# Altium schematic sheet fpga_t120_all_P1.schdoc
size 839 x 594 mm; Symbol: Drawing-Symbol_A4; @Project Name: FPGA_motors_V3_1; @Page Count: 1; @Update Date: 2026-01-04; @Create Date: 2025-12-23; @Schematic Name: fpga_t120_all_p; @Page No: 1; @Page Name: P1; Company: EasyEDA.com; Version: V1.0; Page Size: A4; @Create Time: 13:22:03; @Update Time: 11:05:47; Border: 1; Width: 3304; Height: 2338; Region Start: 1; X Region Count: 6; Y Region Count: 4; Blade Width: 10; Title Block Position: 3; @Board Name: PCB6; Device: Drawing-Symbol_A4
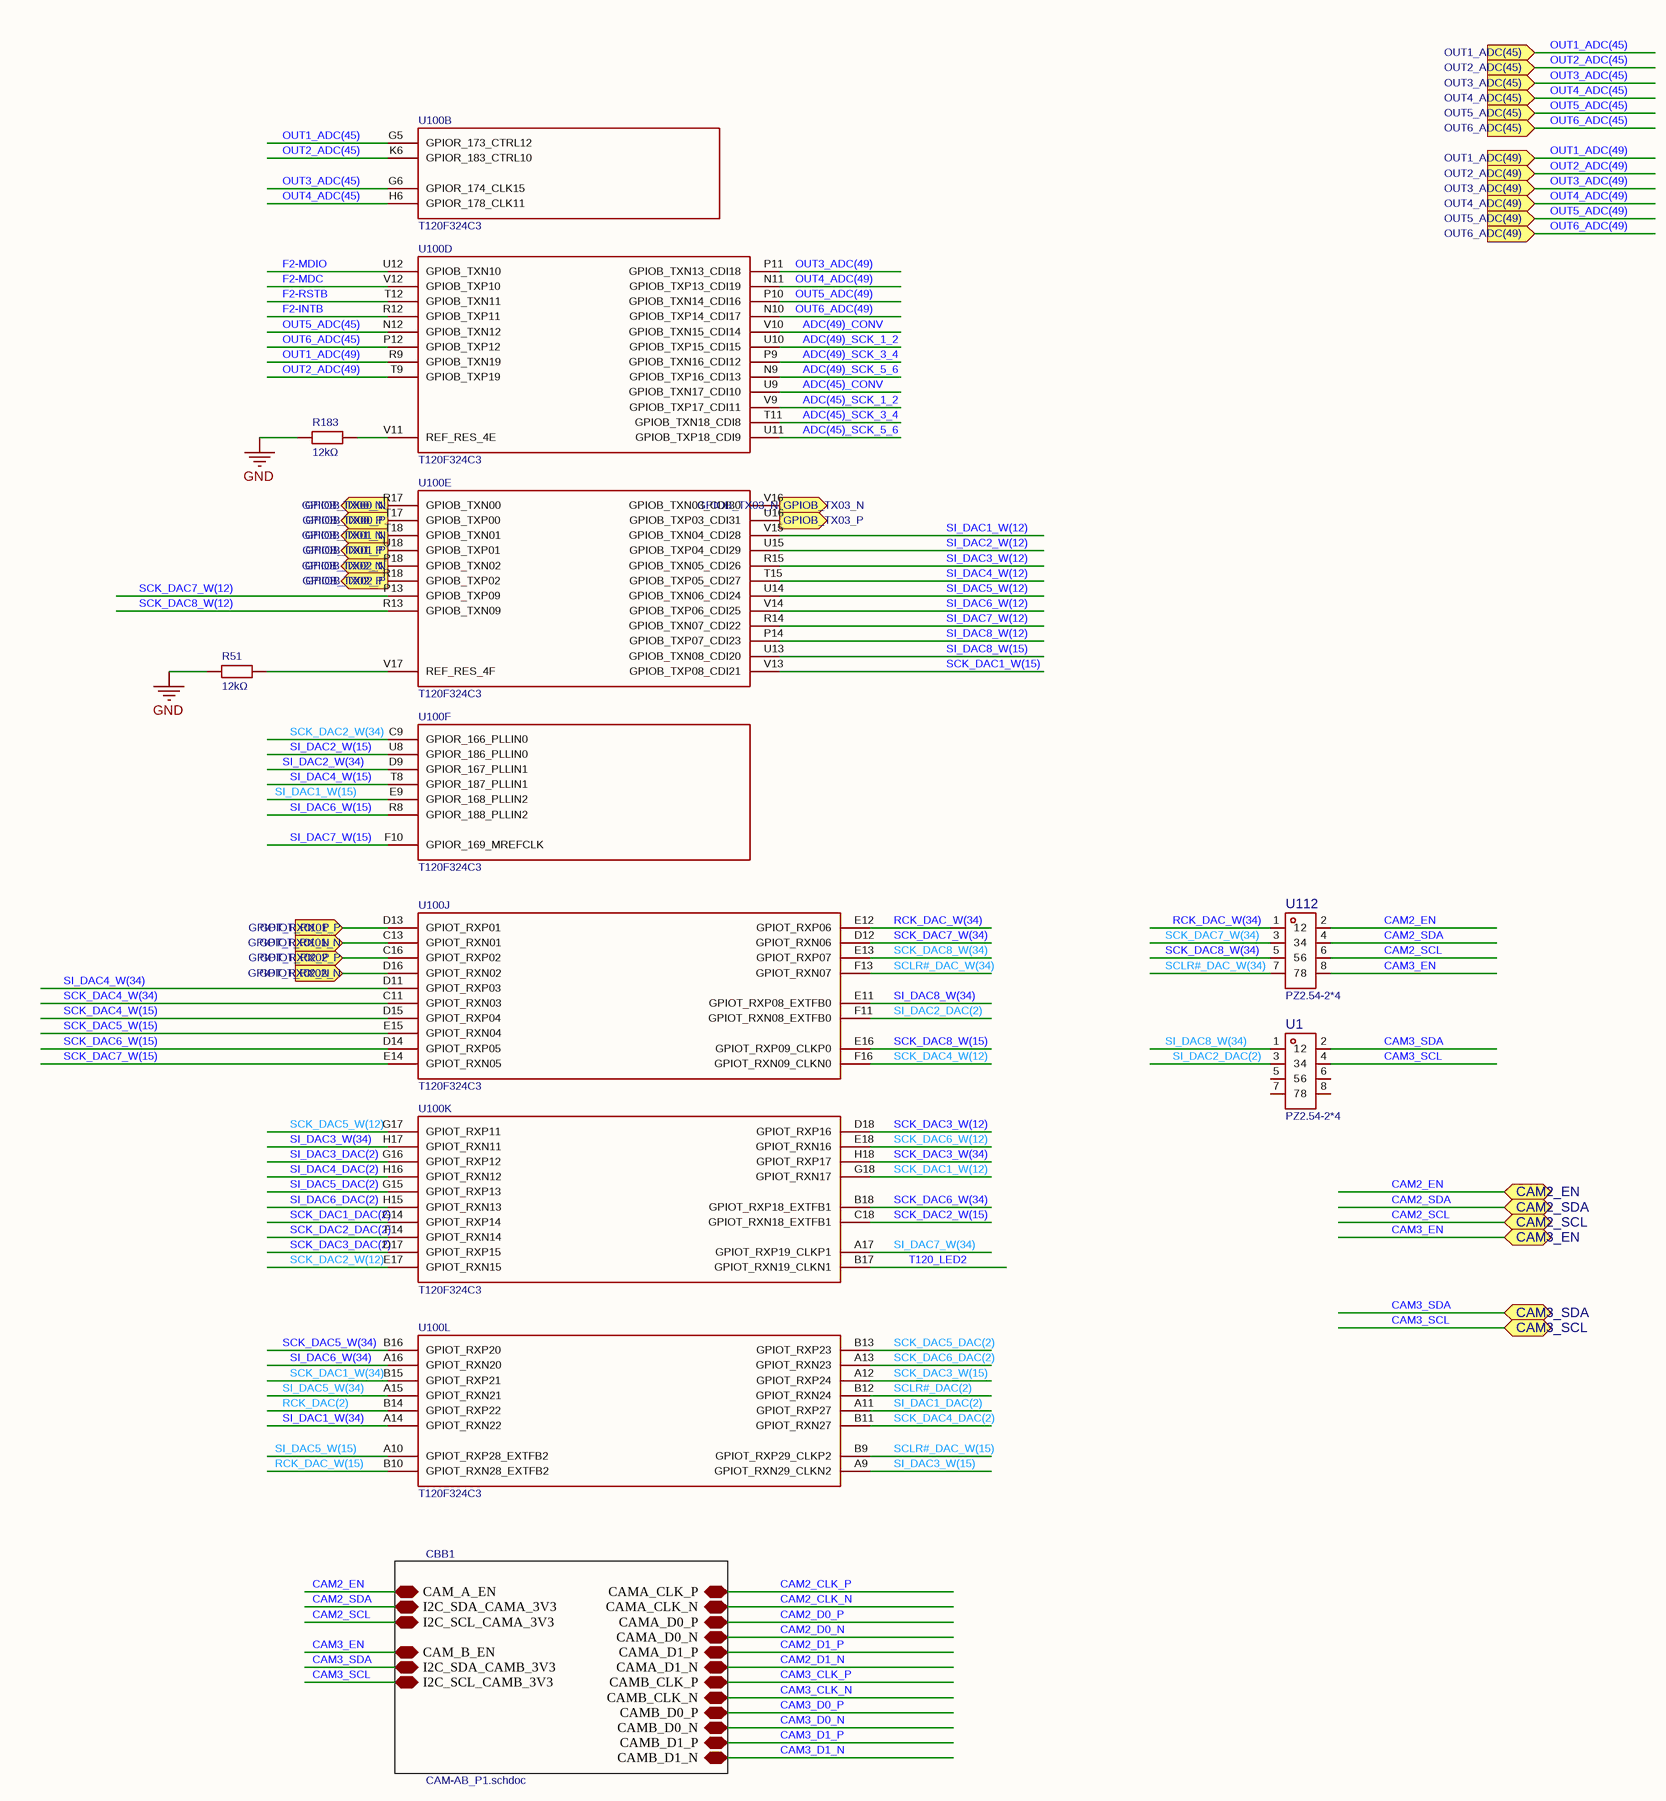
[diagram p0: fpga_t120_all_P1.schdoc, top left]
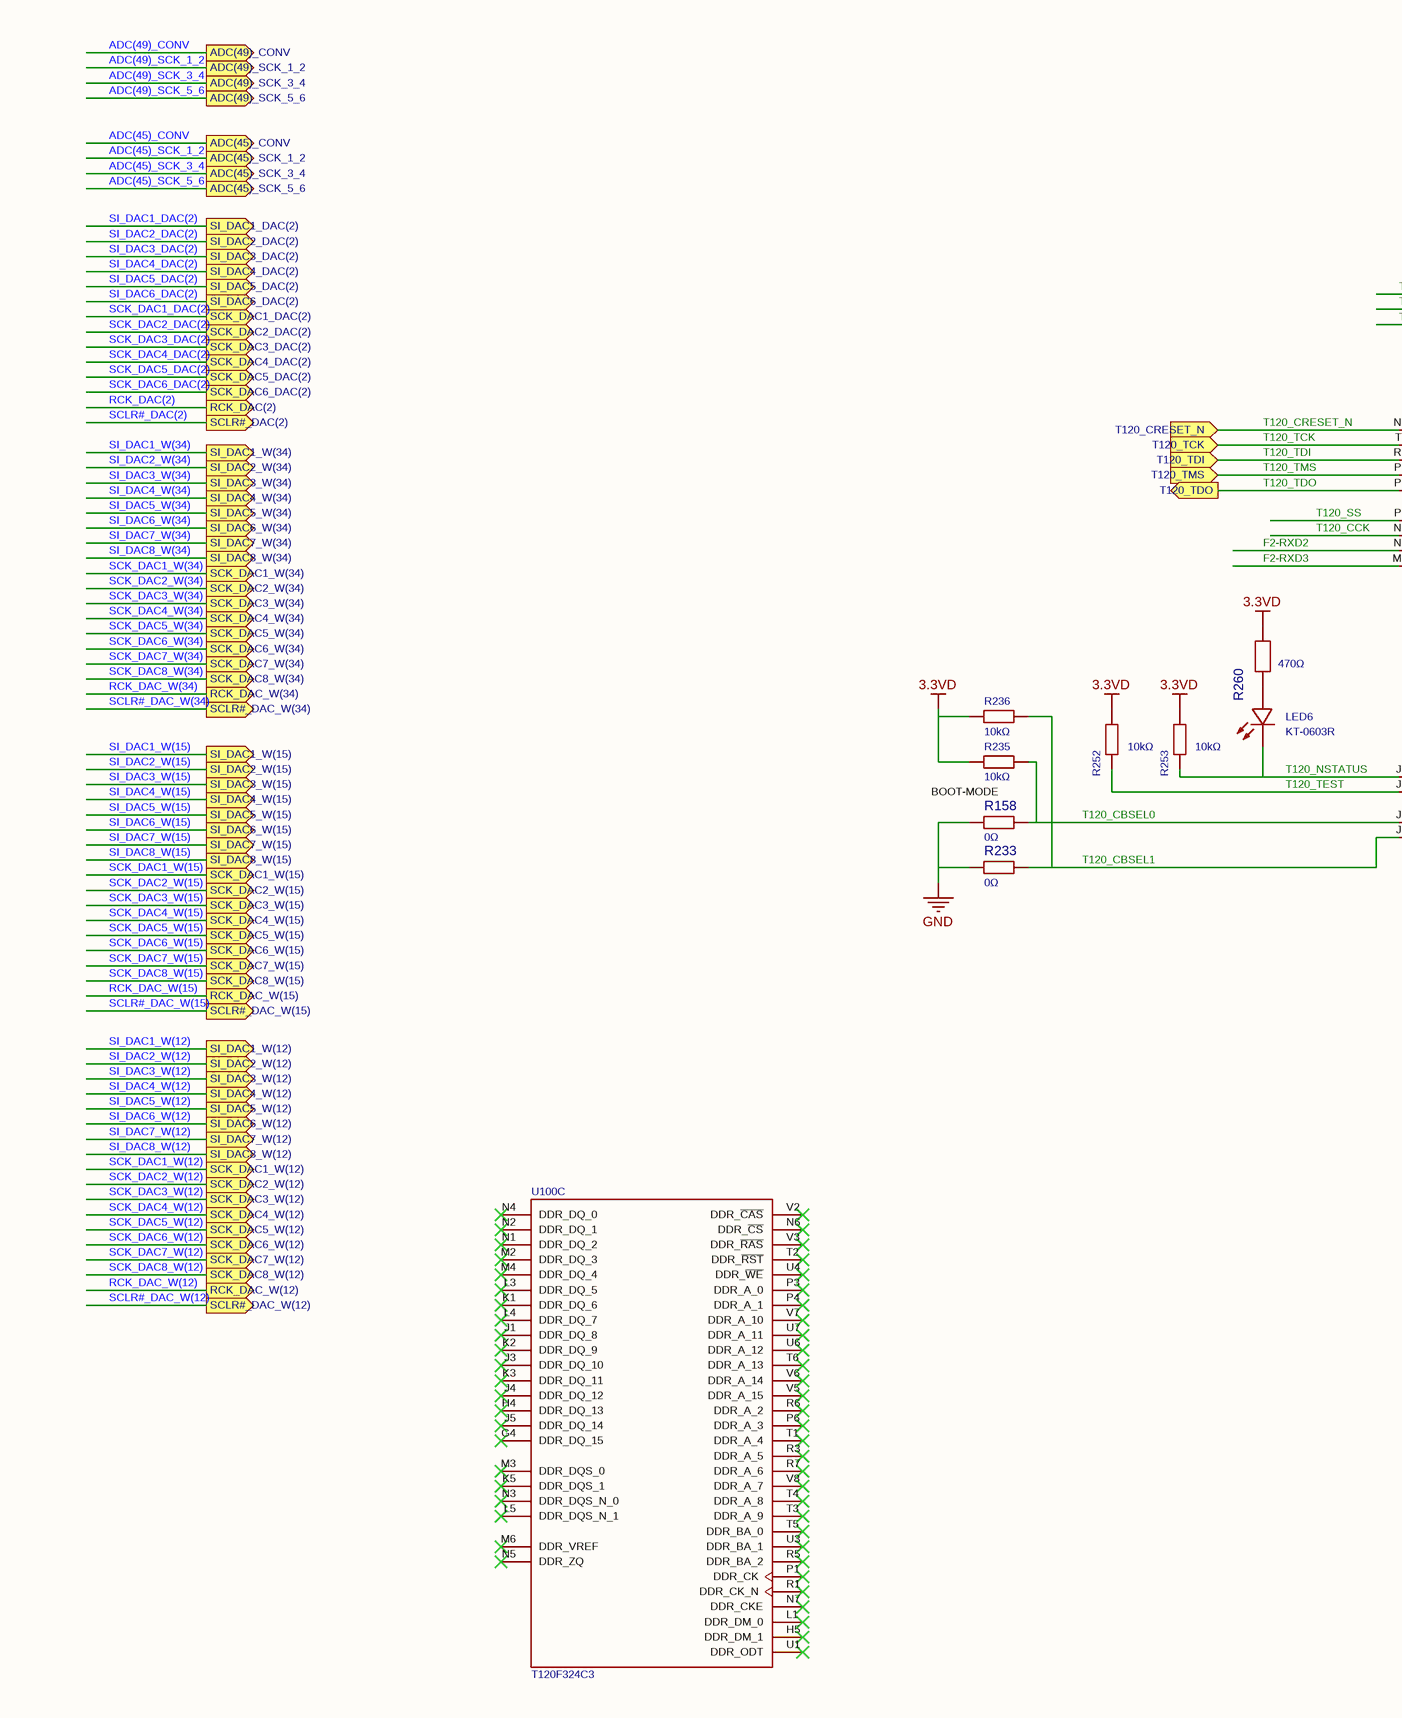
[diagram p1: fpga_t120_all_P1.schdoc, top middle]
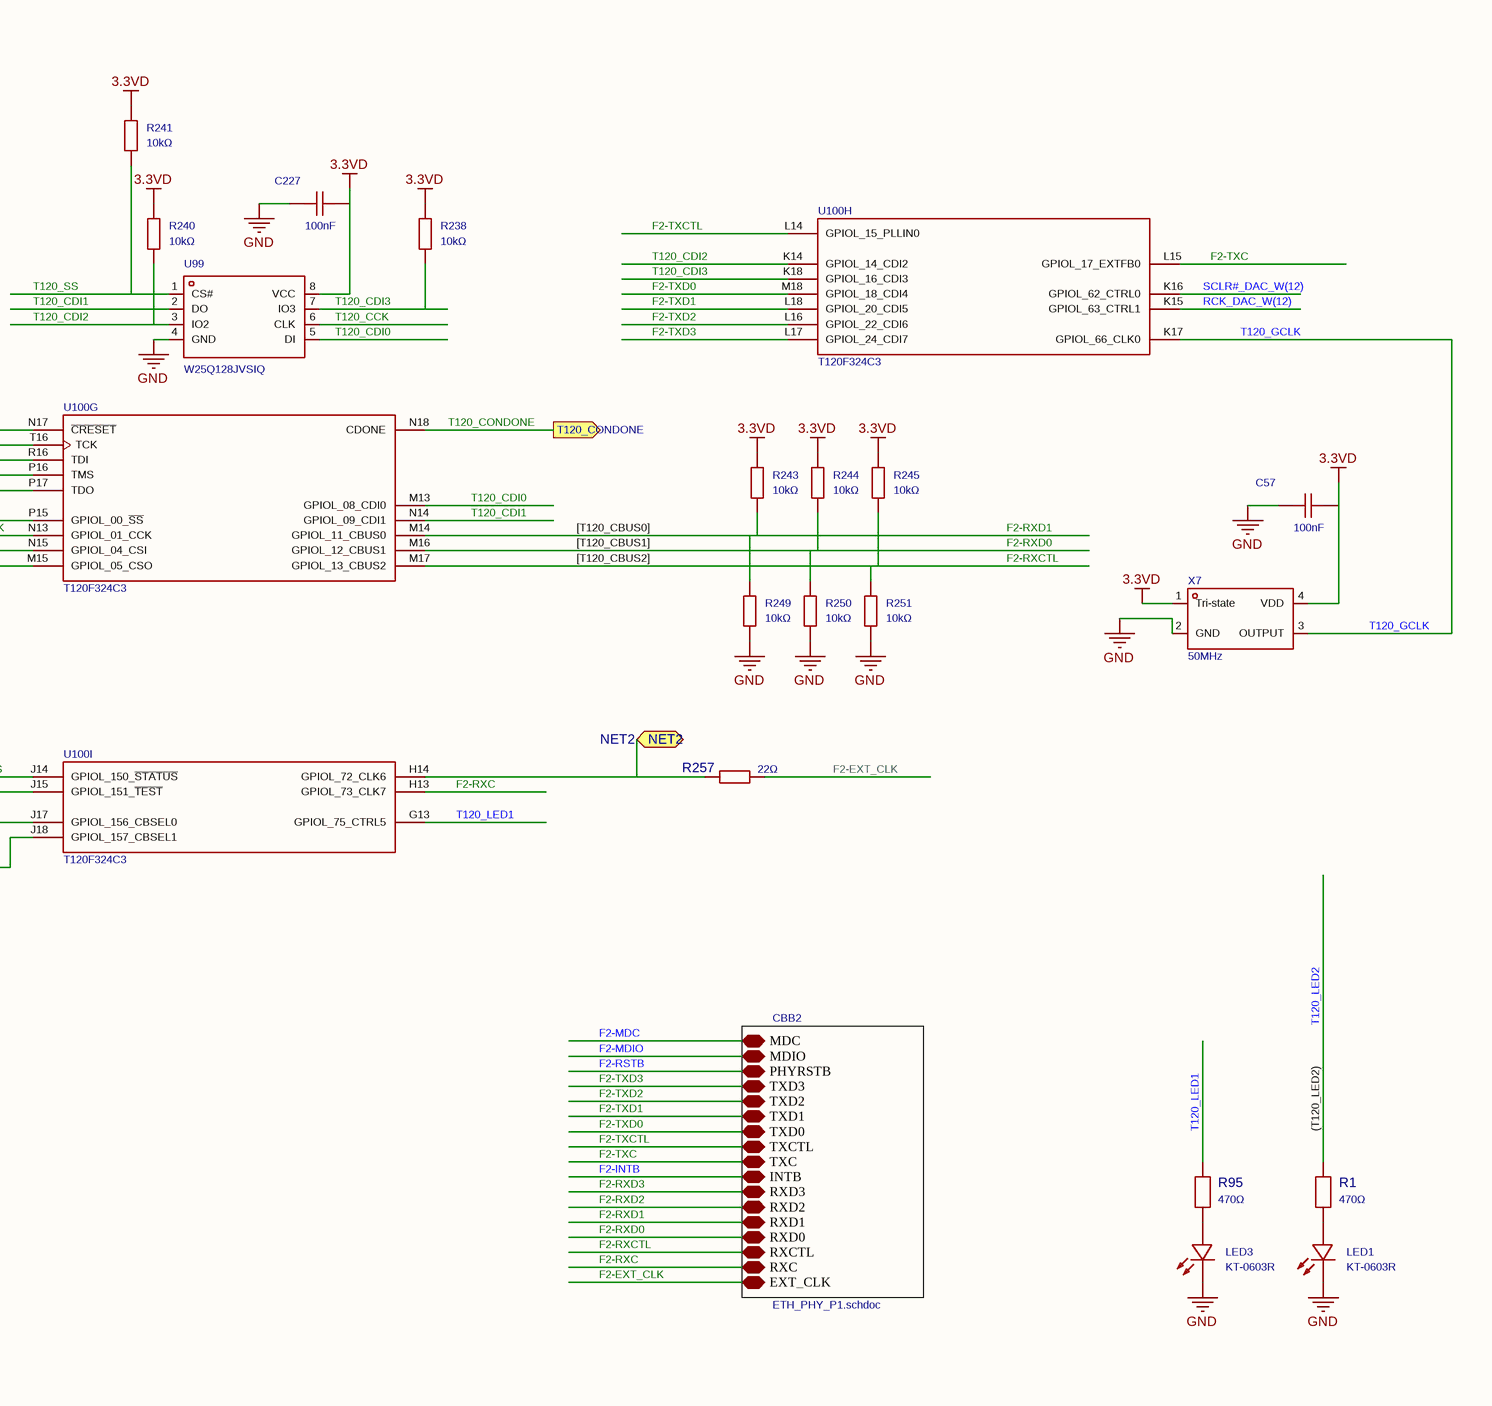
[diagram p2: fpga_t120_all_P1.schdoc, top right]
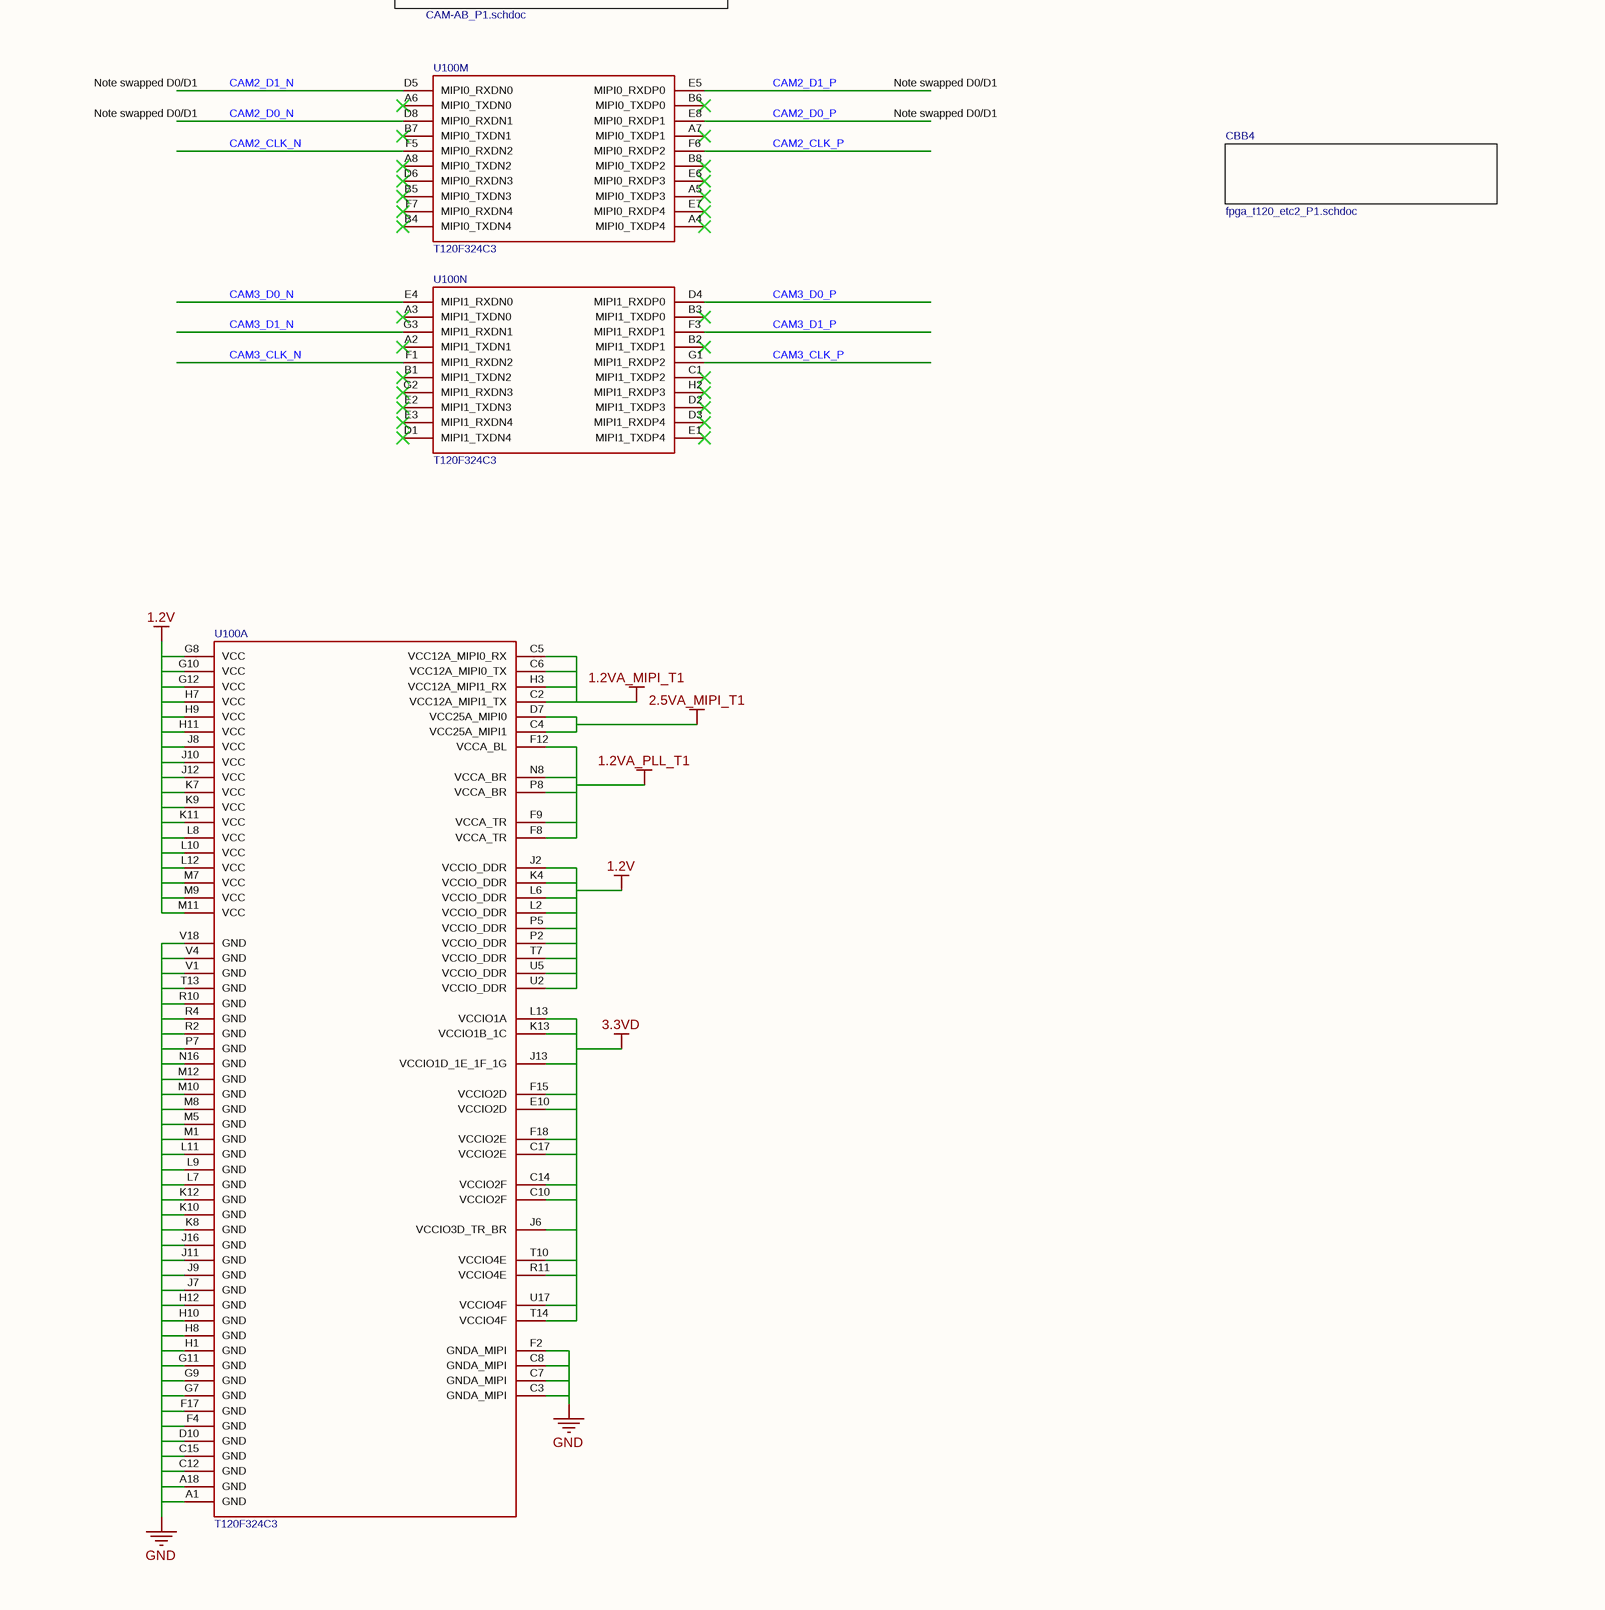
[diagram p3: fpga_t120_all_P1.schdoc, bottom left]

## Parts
C57  100nF  [C0402]
C227  100nF  [C0402]
LED1  KT-0603R  [LED0603-RD]
LED3  KT-0603R  [LED0603-RD]
LED6  KT-0603R  [LED0603-RD]
R1  470Ω  [R0402]
R51  12kΩ  [R0402]
R95  470Ω  [R0402]
R158  0Ω  [R0402]
R183  12kΩ  [R0402]
R233  0Ω  [R0402]
R235  10kΩ  [R0402]
R236  10kΩ  [R0402]
R238  10kΩ  [R0402]
R240  10kΩ  [R0402]
R241  10kΩ  [R0402]
R243  10kΩ  [R0402]
R244  10kΩ  [R0402]
R245  10kΩ  [R0402]
R249  10kΩ  [R0402]
R250  10kΩ  [R0402]
R251  10kΩ  [R0402]
R252  10kΩ  [R0402]
R253  10kΩ  [R0402]
R257  22Ω  [R0402]
R260  470Ω  [R0402]
U1  PZ2.54-2*4  [HDR-TH_8P-P2.54-V-M-R2-C4-S2.54]
U99  W25Q128JVSIQ  [SOIC-8_L5.3-W5.3-P1.27-LS8.0-BL]
U100  T120F324C3  [BGA324C65P18X18_1200X1200X97N]  (parts A,B,C,D,E,F,G,H,I,J,K,L,M,N of 14)
U112  PZ2.54-2*4  [HDR-TH_8P-P2.54-V-M-R2-C4-S2.54]
X7  50MHz  [OSC-SMD_4P-L3.2-W2.5-BL]

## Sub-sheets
CBB1 = CAM-AB_P1.schdoc: CAM_A_EN, CAM_B_EN, I2C_SCL_CAMA_3V3, I2C_SCL_CAMB_3V3, CAMA_CLK_P, CAMA_CLK_N, CAMA_D1_P, CAMA_D1_N, CAMA_D0_P, CAMA_D0_N, CAMB_CLK_P, CAMB_CLK_N, CAMB_D1_P, CAMB_D1_N, CAMB_D0_P, CAMB_D0_N, I2C_SDA_CAMA_3V3, I2C_SDA_CAMB_3V3  | Symbol: CAM-AB
CBB2 = ETH_PHY_P1.schdoc: RXCTL, MDC, PHYRSTB, TXD3, TXD2, TXD1, TXD0, TXCTL, TXC, RXD2, RXD1, RXD0, RXD3, RXC, INTB, MDIO, EXT_CLK  | Symbol: ETH_PHY
CBB4 = fpga_t120_etc2_P1.schdoc: no entries  | Symbol: fpga_t120_etc2

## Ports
ADC(45)_CONV (out), ADC(45)_SCK_1_2 (out), ADC(45)_SCK_3_4 (out), ADC(45)_SCK_5_6 (out), ADC(49)_CONV (out), ADC(49)_SCK_1_2 (out), ADC(49)_SCK_3_4 (out), ADC(49)_SCK_5_6 (out), CAM2_EN (bidir), CAM2_SCL (bidir), CAM2_SDA (bidir), CAM3_EN (bidir), CAM3_SCL (bidir), CAM3_SDA (bidir), GPIOB_TX00_N (out), GPIOB_TX00_P (out), GPIOB_TX01_N (out), GPIOB_TX01_P (out), GPIOB_TX02_N (out), GPIOB_TX02_P (out), GPIOB_TX03_N (out), GPIOB_TX03_P (out), GPIOT_RX01_N (in), GPIOT_RX01_P (in), GPIOT_RX02_N (in), GPIOT_RX02_P (in), NET2 (bidir), OUT1_ADC(45) (in), OUT1_ADC(49) (in), OUT2_ADC(45) (in), OUT2_ADC(49) (in), OUT3_ADC(45) (in), OUT3_ADC(49) (in), OUT4_ADC(45) (in), OUT4_ADC(49) (in), OUT5_ADC(45) (in), OUT5_ADC(49) (in), OUT6_ADC(45) (in), OUT6_ADC(49) (in), RCK_DAC(2) (out), RCK_DAC_W(12) (out), RCK_DAC_W(15) (out), RCK_DAC_W(34) (out), SCK_DAC1_DAC(2) (out), SCK_DAC1_W(12) (out), SCK_DAC1_W(15) (out), SCK_DAC1_W(34) (out), SCK_DAC2_DAC(2) (out), SCK_DAC2_W(12) (out), SCK_DAC2_W(15) (out), SCK_DAC2_W(34) (out), SCK_DAC3_DAC(2) (out), SCK_DAC3_W(12) (out), SCK_DAC3_W(15) (out), SCK_DAC3_W(34) (out), SCK_DAC4_DAC(2) (out), SCK_DAC4_W(12) (out), SCK_DAC4_W(15) (out), SCK_DAC4_W(34) (out), SCK_DAC5_DAC(2) (out), SCK_DAC5_W(12) (out), SCK_DAC5_W(15) (out), SCK_DAC5_W(34) (out), SCK_DAC6_DAC(2) (out), SCK_DAC6_W(12) (out), SCK_DAC6_W(15) (out), SCK_DAC6_W(34) (out), SCK_DAC7_W(12) (out), SCK_DAC7_W(15) (out), SCK_DAC7_W(34) (out), SCK_DAC8_W(12) (out), SCK_DAC8_W(15) (out), SCK_DAC8_W(34) (out), SCLR#_DAC(2) (out), SCLR#_DAC_W(12) (out), SCLR#_DAC_W(15) (out), SCLR#_DAC_W(34) (out), SI_DAC1_DAC(2) (out), SI_DAC1_W(12) (out), SI_DAC1_W(15) (out), SI_DAC1_W(34) (out), SI_DAC2_DAC(2) (out), SI_DAC2_W(12) (out), SI_DAC2_W(15) (out), SI_DAC2_W(34) (out), SI_DAC3_DAC(2) (out), SI_DAC3_W(12) (out), SI_DAC3_W(15) (out), SI_DAC3_W(34) (out), SI_DAC4_DAC(2) (out), SI_DAC4_W(12) (out), SI_DAC4_W(15) (out), SI_DAC4_W(34) (out), SI_DAC5_DAC(2) (out), SI_DAC5_W(12) (out), SI_DAC5_W(15) (out), SI_DAC5_W(34) (out), SI_DAC6_DAC(2) (out), SI_DAC6_W(12) (out), SI_DAC6_W(15) (out), SI_DAC6_W(34) (out), SI_DAC7_W(12) (out), SI_DAC7_W(15) (out), SI_DAC7_W(34) (out), SI_DAC8_W(12) (out), SI_DAC8_W(15) (out), SI_DAC8_W(34) (out), T120_CONDONE (out), T120_CRESET_N (in), T120_TCK (in), T120_TDI (in), T120_TDO (out), T120_TMS (in)

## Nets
1.2V: U100.G8(VCC) U100.G10(VCC) U100.G12(VCC) U100.H7(VCC) U100.H9(VCC) U100.H11(VCC) U100.J2(VCCIO_DDR) U100.J8(VCC) U100.J10(VCC) U100.J12(VCC) U100.K4(VCCIO_DDR) U100.K7(VCC) U100.K9(VCC) U100.K11(VCC) U100.L2(VCCIO_DDR) U100.L6(VCCIO_DDR) U100.L8(VCC) U100.L10(VCC) U100.L12(VCC) U100.M7(VCC) U100.M9(VCC) U100.M11(VCC) U100.P2(VCCIO_DDR) U100.P5(VCCIO_DDR) U100.T7(VCCIO_DDR) U100.U2(VCCIO_DDR) U100.U5(VCCIO_DDR)
1.2VA_MIPI_T1: U100.C2(VCC12A_MIPI1_TX) U100.C5(VCC12A_MIPI0_RX) U100.C6(VCC12A_MIPI0_TX) U100.H3(VCC12A_MIPI1_RX)
1.2VA_PLL_T1: U100.F8(VCCA_TR) U100.F9(VCCA_TR) U100.F12(VCCA_BL) U100.N8(VCCA_BR) U100.P8(VCCA_BR)
2.5VA_MIPI_T1: U100.C4(VCC25A_MIPI1) U100.D7(VCC25A_MIPI0)
3.3VD: C57.1 C227.1 R235.1 R236.1 R238.2 R240.2 R241.2 R243.2 R244.2 R245.2 R252.2 R253.2 R260.2 U99.8(VCC) U100.C10(VCCIO2F) U100.C14(VCCIO2F) U100.C17(VCCIO2E) U100.E10(VCCIO2D) U100.F15(VCCIO2D) U100.F18(VCCIO2E) U100.J6(VCCIO3D_TR_BR) U100.J13(VCCIO1D_1E_1F_1G) U100.K13(VCCIO1B_1C) U100.L13(VCCIO1A) U100.R11(VCCIO4E) U100.T10(VCCIO4E) U100.T14(VCCIO4F) U100.U17(VCCIO4F) X7.1(Tri-state) X7.4(VDD)
GND: C57.2 C227.2 LED1.1(K) LED3.1(K) R51.1 R158.1 R183.1 R233.1 R249.1 R250.1 R251.1 U99.4(GND) U100.A1(GND) U100.A18(GND) U100.C3(GNDA_MIPI) U100.C7(GNDA_MIPI) U100.C8(GNDA_MIPI) U100.C12(GND) U100.C15(GND) U100.D10(GND) U100.F2(GNDA_MIPI) U100.F4(GND) U100.F17(GND) U100.G7(GND) U100.G9(GND) U100.G11(GND) U100.H1(GND) U100.H8(GND) U100.H10(GND) U100.H12(GND) U100.J7(GND) U100.J9(GND) U100.J11(GND) U100.J16(GND) U100.K8(GND) U100.K10(GND) U100.K12(GND) U100.L7(GND) U100.L9(GND) U100.L11(GND) U100.M1(GND) U100.M5(GND) U100.M8(GND) U100.M10(GND) U100.M12(GND) U100.N16(GND) U100.P7(GND) U100.R2(GND) U100.R4(GND) U100.R10(GND) U100.T13(GND) U100.V1(GND) U100.V4(GND) U100.V18(GND) X7.2(GND)
ADC(45)_CONV: U100.U9(GPIOB_TXN17_CDI10) ; port ADC(45)_CONV
ADC(45)_SCK_1_2: U100.V9(GPIOB_TXP17_CDI11) ; port ADC(45)_SCK_1_2
ADC(45)_SCK_3_4: U100.T11(GPIOB_TXN18_CDI8) ; port ADC(45)_SCK_3_4
ADC(45)_SCK_5_6: U100.U11(GPIOB_TXP18_CDI9) ; port ADC(45)_SCK_5_6
ADC(49)_CONV: U100.V10(GPIOB_TXN15_CDI14) ; port ADC(49)_CONV
ADC(49)_SCK_1_2: U100.U10(GPIOB_TXP15_CDI15) ; port ADC(49)_SCK_1_2
ADC(49)_SCK_3_4: U100.P9(GPIOB_TXN16_CDI12) ; port ADC(49)_SCK_3_4
ADC(49)_SCK_5_6: U100.N9(GPIOB_TXP16_CDI13) ; port ADC(49)_SCK_5_6
CAM2_CLK_N: U100.F5(MIPI0_RXDN2) ; sheet CBB1/CAMA_CLK_N
CAM2_CLK_P: U100.F6(MIPI0_RXDP2) ; sheet CBB1/CAMA_CLK_P
CAM2_D0_N: U100.D8(MIPI0_RXDN1) ; sheet CBB1/CAMA_D0_N
CAM2_D0_P: U100.E8(MIPI0_RXDP1) ; sheet CBB1/CAMA_D0_P
CAM2_D1_N: U100.D5(MIPI0_RXDN0) ; sheet CBB1/CAMA_D1_N
CAM2_D1_P: U100.E5(MIPI0_RXDP0) ; sheet CBB1/CAMA_D1_P
CAM2_EN: U112.2 ; port CAM2_EN, sheet CBB1/CAM_A_EN
CAM2_SCL: U112.6 ; port CAM2_SCL, sheet CBB1/I2C_SCL_CAMA_3V3
CAM2_SDA: U112.4 ; port CAM2_SDA, sheet CBB1/I2C_SDA_CAMA_3V3
CAM3_CLK_N: U100.F1(MIPI1_RXDN2) ; sheet CBB1/CAMB_CLK_N
CAM3_CLK_P: U100.G1(MIPI1_RXDP2) ; sheet CBB1/CAMB_CLK_P
CAM3_D0_N: U100.E4(MIPI1_RXDN0) ; sheet CBB1/CAMB_D0_N
CAM3_D0_P: U100.D4(MIPI1_RXDP0) ; sheet CBB1/CAMB_D0_P
CAM3_D1_N: U100.G3(MIPI1_RXDN1) ; sheet CBB1/CAMB_D1_N
CAM3_D1_P: U100.F3(MIPI1_RXDP1) ; sheet CBB1/CAMB_D1_P
CAM3_EN: U112.8 ; port CAM3_EN, sheet CBB1/CAM_B_EN
CAM3_SCL: U1.4 ; port CAM3_SCL, sheet CBB1/I2C_SCL_CAMB_3V3
CAM3_SDA: U1.2 ; port CAM3_SDA, sheet CBB1/I2C_SDA_CAMB_3V3
F2-EXT_CLK: R257.2 ; sheet CBB2/EXT_CLK
F2-INTB: U100.R12(GPIOB_TXP11) ; sheet CBB2/INTB
F2-MDC: U100.V12(GPIOB_TXP10) ; sheet CBB2/MDC
F2-MDIO: U100.U12(GPIOB_TXN10) ; sheet CBB2/MDIO
F2-RSTB: U100.T12(GPIOB_TXN11) ; sheet CBB2/PHYRSTB
F2-RXC: U100.H13(GPIOL_73_CLK7) ; sheet CBB2/RXC
F2-RXCTL: R245.1 R251.2 U100.M17(GPIOL_13_CBUS2) ; sheet CBB2/RXCTL
F2-RXD0: R244.1 R250.2 U100.M16(GPIOL_12_CBUS1) ; sheet CBB2/RXD0
F2-RXD1: R243.1 R249.2 U100.M14(GPIOL_11_CBUS0) ; sheet CBB2/RXD1
F2-RXD2: U100.N15(GPIOL_04_CSI) ; sheet CBB2/RXD2
F2-RXD3: U100.M15(GPIOL_05_CSO) ; sheet CBB2/RXD3
F2-TXC: U100.L15(GPIOL_17_EXTFB0) ; sheet CBB2/TXC
F2-TXCTL: U100.L14(GPIOL_15_PLLIN0) ; sheet CBB2/TXCTL
F2-TXD0: U100.M18(GPIOL_18_CDI4) ; sheet CBB2/TXD0
F2-TXD1: U100.L18(GPIOL_20_CDI5) ; sheet CBB2/TXD1
F2-TXD2: U100.L16(GPIOL_22_CDI6) ; sheet CBB2/TXD2
F2-TXD3: U100.L17(GPIOL_24_CDI7) ; sheet CBB2/TXD3
GPIOB_TX00_N: U100.R17(GPIOB_TXN00) ; port GPIOB_TX00_N
GPIOB_TX00_P: U100.T17(GPIOB_TXP00) ; port GPIOB_TX00_P
GPIOB_TX01_N: U100.T18(GPIOB_TXN01) ; port GPIOB_TX01_N
GPIOB_TX01_P: U100.U18(GPIOB_TXP01) ; port GPIOB_TX01_P
GPIOB_TX02_N: U100.P18(GPIOB_TXN02) ; port GPIOB_TX02_N
GPIOB_TX02_P: U100.R18(GPIOB_TXP02) ; port GPIOB_TX02_P
GPIOB_TX03_N: U100.V16(GPIOB_TXN03_CDI30) ; port GPIOB_TX03_N
GPIOB_TX03_P: U100.U16(GPIOB_TXP03_CDI31) ; port GPIOB_TX03_P
GPIOT_RX01_N: U100.C13(GPIOT_RXN01) ; port GPIOT_RX01_N
GPIOT_RX01_P: U100.D13(GPIOT_RXP01) ; port GPIOT_RX01_P
GPIOT_RX02_N: U100.D16(GPIOT_RXN02) ; port GPIOT_RX02_N
GPIOT_RX02_P: U100.C16(GPIOT_RXP02) ; port GPIOT_RX02_P
NET2: R257.1 U100.H14(GPIOL_72_CLK6) ; port NET2
OUT1_ADC(45): U100.G5(GPIOR_173_CTRL12) ; port OUT1_ADC(45)
OUT1_ADC(49): U100.R9(GPIOB_TXN19) ; port OUT1_ADC(49)
OUT2_ADC(45): U100.K6(GPIOR_183_CTRL10) ; port OUT2_ADC(45)
OUT2_ADC(49): U100.T9(GPIOB_TXP19) ; port OUT2_ADC(49)
OUT3_ADC(45): U100.G6(GPIOR_174_CLK15) ; port OUT3_ADC(45)
OUT3_ADC(49): U100.P11(GPIOB_TXN13_CDI18) ; port OUT3_ADC(49)
OUT4_ADC(45): U100.H6(GPIOR_178_CLK11) ; port OUT4_ADC(45)
OUT4_ADC(49): U100.N11(GPIOB_TXP13_CDI19) ; port OUT4_ADC(49)
OUT5_ADC(45): U100.N12(GPIOB_TXN12) ; port OUT5_ADC(45)
OUT5_ADC(49): U100.P10(GPIOB_TXN14_CDI16) ; port OUT5_ADC(49)
OUT6_ADC(45): U100.P12(GPIOB_TXP12) ; port OUT6_ADC(45)
OUT6_ADC(49): U100.N10(GPIOB_TXP14_CDI17) ; port OUT6_ADC(49)
RCK_DAC(2): U100.B14(GPIOT_RXP22) ; port RCK_DAC(2)
RCK_DAC_W(12): U100.K15(GPIOL_63_CTRL1) ; port RCK_DAC_W(12)
RCK_DAC_W(15): U100.B10(GPIOT_RXN28_EXTFB2) ; port RCK_DAC_W(15)
RCK_DAC_W(34): U100.E12(GPIOT_RXP06) U112.1 ; port RCK_DAC_W(34)
SCK_DAC1_DAC(2): U100.G14(GPIOT_RXP14) ; port SCK_DAC1_DAC(2)
SCK_DAC1_W(12): U100.G18(GPIOT_RXN17) ; port SCK_DAC1_W(12)
SCK_DAC1_W(15): U100.V13(GPIOB_TXP08_CDI21) ; port SCK_DAC1_W(15)
SCK_DAC1_W(34): U100.B15(GPIOT_RXP21) ; port SCK_DAC1_W(34)
SCK_DAC2_DAC(2): U100.F14(GPIOT_RXN14) ; port SCK_DAC2_DAC(2)
SCK_DAC2_W(12): U100.E17(GPIOT_RXN15) ; port SCK_DAC2_W(12)
SCK_DAC2_W(15): U100.C18(GPIOT_RXN18_EXTFB1) ; port SCK_DAC2_W(15)
SCK_DAC2_W(34): U100.C9(GPIOR_166_PLLIN0) ; port SCK_DAC2_W(34)
SCK_DAC3_DAC(2): U100.D17(GPIOT_RXP15) ; port SCK_DAC3_DAC(2)
SCK_DAC3_W(12): U100.D18(GPIOT_RXP16) ; port SCK_DAC3_W(12)
SCK_DAC3_W(15): U100.A12(GPIOT_RXP24) ; port SCK_DAC3_W(15)
SCK_DAC3_W(34): U100.H18(GPIOT_RXP17) ; port SCK_DAC3_W(34)
SCK_DAC4_DAC(2): U100.B11(GPIOT_RXN27) ; port SCK_DAC4_DAC(2)
SCK_DAC4_W(12): U100.F16(GPIOT_RXN09_CLKN0) ; port SCK_DAC4_W(12)
SCK_DAC4_W(15): U100.D15(GPIOT_RXP04) ; port SCK_DAC4_W(15)
SCK_DAC4_W(34): U100.C11(GPIOT_RXN03) ; port SCK_DAC4_W(34)
SCK_DAC5_DAC(2): U100.B13(GPIOT_RXP23) ; port SCK_DAC5_DAC(2)
SCK_DAC5_W(12): U100.G17(GPIOT_RXP11) ; port SCK_DAC5_W(12)
SCK_DAC5_W(15): U100.E15(GPIOT_RXN04) ; port SCK_DAC5_W(15)
SCK_DAC5_W(34): U100.B16(GPIOT_RXP20) ; port SCK_DAC5_W(34)
SCK_DAC6_DAC(2): U100.A13(GPIOT_RXN23) ; port SCK_DAC6_DAC(2)
SCK_DAC6_W(12): U100.E18(GPIOT_RXN16) ; port SCK_DAC6_W(12)
SCK_DAC6_W(15): U100.D14(GPIOT_RXP05) ; port SCK_DAC6_W(15)
SCK_DAC6_W(34): U100.B18(GPIOT_RXP18_EXTFB1) ; port SCK_DAC6_W(34)
SCK_DAC7_W(12): U100.P13(GPIOB_TXP09) ; port SCK_DAC7_W(12)
SCK_DAC7_W(15): U100.E14(GPIOT_RXN05) ; port SCK_DAC7_W(15)
SCK_DAC7_W(34): U100.D12(GPIOT_RXN06) U112.3 ; port SCK_DAC7_W(34)
SCK_DAC8_W(12): U100.R13(GPIOB_TXN09) ; port SCK_DAC8_W(12)
SCK_DAC8_W(15): U100.E16(GPIOT_RXP09_CLKP0) ; port SCK_DAC8_W(15)
SCK_DAC8_W(34): U100.E13(GPIOT_RXP07) U112.5 ; port SCK_DAC8_W(34)
SCLR#_DAC(2): U100.B12(GPIOT_RXN24) ; port SCLR#_DAC(2)
SCLR#_DAC_W(12): U100.K16(GPIOL_62_CTRL0) ; port SCLR#_DAC_W(12)
SCLR#_DAC_W(15): U100.B9(GPIOT_RXP29_CLKP2) ; port SCLR#_DAC_W(15)
SCLR#_DAC_W(34): U100.F13(GPIOT_RXN07) U112.7 ; port SCLR#_DAC_W(34)
SI_DAC1_DAC(2): U100.A11(GPIOT_RXP27) ; port SI_DAC1_DAC(2)
SI_DAC1_W(12): U100.V15(GPIOB_TXN04_CDI28) ; port SI_DAC1_W(12)
SI_DAC1_W(15): U100.E9(GPIOR_168_PLLIN2) ; port SI_DAC1_W(15)
SI_DAC1_W(34): U100.A14(GPIOT_RXN22) ; port SI_DAC1_W(34)
SI_DAC2_DAC(2): U1.3 U100.F11(GPIOT_RXN08_EXTFB0) ; port SI_DAC2_DAC(2)
SI_DAC2_W(12): U100.U15(GPIOB_TXP04_CDI29) ; port SI_DAC2_W(12)
SI_DAC2_W(15): U100.U8(GPIOR_186_PLLIN0) ; port SI_DAC2_W(15)
SI_DAC2_W(34): U100.D9(GPIOR_167_PLLIN1) ; port SI_DAC2_W(34)
SI_DAC3_DAC(2): U100.G16(GPIOT_RXP12) ; port SI_DAC3_DAC(2)
SI_DAC3_W(12): U100.R15(GPIOB_TXN05_CDI26) ; port SI_DAC3_W(12)
SI_DAC3_W(15): U100.A9(GPIOT_RXN29_CLKN2) ; port SI_DAC3_W(15)
SI_DAC3_W(34): U100.H17(GPIOT_RXN11) ; port SI_DAC3_W(34)
SI_DAC4_DAC(2): U100.H16(GPIOT_RXN12) ; port SI_DAC4_DAC(2)
SI_DAC4_W(12): U100.T15(GPIOB_TXP05_CDI27) ; port SI_DAC4_W(12)
SI_DAC4_W(15): U100.T8(GPIOR_187_PLLIN1) ; port SI_DAC4_W(15)
SI_DAC4_W(34): U100.D11(GPIOT_RXP03) ; port SI_DAC4_W(34)
SI_DAC5_DAC(2): U100.G15(GPIOT_RXP13) ; port SI_DAC5_DAC(2)
SI_DAC5_W(12): U100.U14(GPIOB_TXN06_CDI24) ; port SI_DAC5_W(12)
SI_DAC5_W(15): U100.A10(GPIOT_RXP28_EXTFB2) ; port SI_DAC5_W(15)
SI_DAC5_W(34): U100.A15(GPIOT_RXN21) ; port SI_DAC5_W(34)
SI_DAC6_DAC(2): U100.H15(GPIOT_RXN13) ; port SI_DAC6_DAC(2)
SI_DAC6_W(12): U100.V14(GPIOB_TXP06_CDI25) ; port SI_DAC6_W(12)
SI_DAC6_W(15): U100.R8(GPIOR_188_PLLIN2) ; port SI_DAC6_W(15)
SI_DAC6_W(34): U100.A16(GPIOT_RXN20) ; port SI_DAC6_W(34)
SI_DAC7_W(12): U100.R14(GPIOB_TXN07_CDI22) ; port SI_DAC7_W(12)
SI_DAC7_W(15): U100.F10(GPIOR_169_MREFCLK) ; port SI_DAC7_W(15)
SI_DAC7_W(34): U100.A17(GPIOT_RXP19_CLKP1) ; port SI_DAC7_W(34)
SI_DAC8_W(12): U100.P14(GPIOB_TXP07_CDI23) ; port SI_DAC8_W(12)
SI_DAC8_W(15): U100.U13(GPIOB_TXN08_CDI20) ; port SI_DAC8_W(15)
SI_DAC8_W(34): U1.1 U100.E11(GPIOT_RXP08_EXTFB0) ; port SI_DAC8_W(34)
T120_CBSEL0: R158.2 R235.2 U100.J17(GPIOL_156_CBSEL0)
T120_CBSEL1: R233.2 R236.2 U100.J18(GPIOL_157_CBSEL1)
T120_CCK: U99.6(CLK) U100.N13(GPIOL_01_CCK)
T120_CDI0: U99.5(DI) U100.M13(GPIOL_08_CDI0)
T120_CDI1: U99.2(DO) U100.N14(GPIOL_09_CDI1)
T120_CDI2: R240.1 U99.3(IO2) U100.K14(GPIOL_14_CDI2)
T120_CDI3: R238.1 U99.7(IO3) U100.K18(GPIOL_16_CDI3)
T120_CONDONE: U100.N18(CDONE) ; port T120_CONDONE
T120_CRESET_N: U100.N17(~{CRESET}) ; port T120_CRESET_N
T120_GCLK: U100.K17(GPIOL_66_CLK0) X7.3(OUTPUT)
T120_LED1: R95.2 U100.G13(GPIOL_75_CTRL5)
T120_LED2: R1.2 U100.B17(GPIOT_RXN19_CLKN1)
T120_NSTATUS: LED6.1(K) R253.1 U100.J14(GPIOL_150_~{STATUS})
T120_SS: R241.1 U99.1(CS#) U100.P15(GPIOL_00_~{SS})
T120_TCK: U100.T16(TCK) ; port T120_TCK
T120_TDI: U100.R16(TDI) ; port T120_TDI
T120_TDO: U100.P17(TDO) ; port T120_TDO
T120_TEST: R252.1 U100.J15(GPIOL_151_~{TEST})
T120_TMS: U100.P16(TMS) ; port T120_TMS
NetLED1_2: LED1.2(A) R1.1
NetLED3_2: LED3.2(A) R95.1
NetLED6_2: LED6.2(A) R260.1
NetR51_2: R51.2 U100.V17(REF_RES_4F)
NetR183_2: R183.2 U100.V11(REF_RES_4E)

Not connected (* = marked no-connect by the designer): U1 5 6 7 8; U100 A2(MIPI1_TXDN1)* A3(MIPI1_TXDN0)* A4(MIPI0_TXDP4)* A5(MIPI0_TXDP3)* A6(MIPI0_TXDN0)* A7(MIPI0_TXDP1)* A8(MIPI0_TXDN2)* B1(MIPI1_TXDN2)* B2(MIPI1_TXDP1)* B3(MIPI1_TXDP0)* B4(MIPI0_TXDN4)* B5(MIPI0_TXDN3)* B6(MIPI0_TXDP0)* B7(MIPI0_TXDN1)* B8(MIPI0_TXDP2)* C1(MIPI1_TXDP2)* D1(MIPI1_TXDN4)* D2(MIPI1_TXDP3)* D3(MIPI1_RXDP4)* D6(MIPI0_RXDN3)* E1(MIPI1_TXDP4)* E2(MIPI1_TXDN3)* E3(MIPI1_RXDN4)* E6(MIPI0_RXDP3)* E7(MIPI0_RXDP4)* F7(MIPI0_RXDN4)* G2(MIPI1_RXDN3)* G4(DDR_DQ_15)* H2(MIPI1_RXDP3)* H4(DDR_DQ_13)* H5(DDR_DM_1)* J1(DDR_DQ_8)* J3(DDR_DQ_10)* J4(DDR_DQ_12)* J5(DDR_DQ_14)* K1(DDR_DQ_6)* K2(DDR_DQ_9)* K3(DDR_DQ_11)* K5(DDR_DQS_1)* L1(DDR_DM_0)* L3(DDR_DQ_5)* L4(DDR_DQ_7)* L5(DDR_DQS_N_1)* M2(DDR_DQ_3)* M3(DDR_DQS_0)* M4(DDR_DQ_4)* M6(DDR_VREF)* N1(DDR_DQ_2)* N2(DDR_DQ_1)* N3(DDR_DQS_N_0)* N4(DDR_DQ_0)* N5(DDR_ZQ)* N6(DDR_~{CS})* N7(DDR_CKE)* P1(DDR_CK)* P3(DDR_A_0)* P4(DDR_A_1)* P6(DDR_A_3)* R1(DDR_CK_N)* R3(DDR_A_5)* R5(DDR_BA_2)* R6(DDR_A_2)* R7(DDR_A_6)* T1(DDR_A_4)* T2(DDR_~{RST})* T3(DDR_A_9)* T4(DDR_A_8)* T5(DDR_BA_0)* T6(DDR_A_13)* U1(DDR_ODT)* U3(DDR_BA_1)* U4(DDR_~{WE})* U6(DDR_A_12)* U7(DDR_A_11)* V2(DDR_~{CAS})* V3(DDR_~{RAS})* V5(DDR_A_15)* V6(DDR_A_14)* V7(DDR_A_10)* V8(DDR_A_7)*

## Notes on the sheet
- [T120_CBUS0]
- [T120_CBUS1]
- [T120_CBUS2]
- BOOT-MODE
- (near R1) (T120_LED2)
- Note swapped D0/D1

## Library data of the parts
C57 C227 = CL05B104KB54PNC: Capacitance: Tolerance:±10% Tolerance:±10% Voltage Rated: Temperature Coefficient:; Manufacturer: SAMSUNG(三星); Check: true; AddInBom: yes; ModelId: b7d13df3e9464d7a99d0651d1a5b4d57; ModelName: C0402_L1.0-W0.5-H0.5; ModelTransform: 39.37,19.685,0,0,0,0,0,0,0; Tolerance: ±10%
LED1 = KT-0603R: Emitted Color:Red Power Dissipation:- Forward Current:- Dominant Wavelength:- Dominant Wavelength:- Peak Wavelength:- Diode Configuration:- Lens Color:- Color Temperature:- Color Temperature:- Viewing Angle:- Mounting Sytle:- Operating Temperature:-40℃~+8; Manufacturer: KENTO; 3D Model: 5e3b568068dd46cf8019c1d1baa0031b; 3D Model Transform: 63.7794,32.283,0,0,0,0,0,0,0; Emitted Color: Red; AddInBom: yes
LED3 LED6 = KT-0603R: Emitted Color:Red Power Dissipation:- Forward Current:- Dominant Wavelength:- Dominant Wavelength:- Peak Wavelength:- Diode Configuration:- Lens Color:- Color Temperature:- Color Temperature:- Viewing Angle:- Mounting Sytle:- Operating Temperature:-40℃~+8; Manufacturer: KENTO; AddInBom: yes; ModelId: 5e3b568068dd46cf8019c1d1baa0031b; ModelTransform: 63.7794,32.283,0,0,0,0,0,0,0; Emitted Color: Red
R1 = 0402WGF4700TCE: Type:Thick Film Resistors Resistance: Tolerance:±1% Tolerance:±1% Power(Watts): Overload Voltage (Max): Temperature Coefficient:±100ppm/℃ Temperature Coefficient:±100ppm/℃ Operating Temperature Range:-55℃~+155℃ Operating Temperature Range:-55℃~+155℃; Manufacturer: UNI-ROYAL(厚声); Symbol: ERJ2RKF4700X; 3D Model: efdecb7dae4442949d28eecaf748420f; 3D Model Transform: 39.37,19.685,0,0,0,0,0,0,0; Tolerance: ±1%; AddInBom: yes; ModelName: R0402_L1.0-W0.5-H0.4
R51 R183 = 0402WGF1202TCE: Type:Thick Film Resistor Resistance:12kΩ Tolerance:±1% Tolerance:±1% Power(Watts):62.5mW Voltage-Supply(Max):50V Temperature Coefficient:±100ppm/℃ Temperature Coefficient:±100ppm/℃ Operating Temperature:-55℃~+155℃ Operating Temperature:-55℃~+155℃; Manufacturer: UNI-ROYAL(厚声); AddInBom: yes; ModelId: efdecb7dae4442949d28eecaf748420f0819f05c4eef4c71ace90d822a990e87; ModelName: R0402_L1.0-W0.5-H0.4; ModelTransform: 39.37,19.685,0,0,0,0,0,0,0; Tolerance: ±1%; Power(Watts): 62.5mW; Voltage-Supply(Max): 50V
R95 R260 = 0402WGF4700TCE: Type:Thick Film Resistors Resistance: Tolerance:±1% Tolerance:±1% Power(Watts): Overload Voltage (Max): Temperature Coefficient:±100ppm/℃ Temperature Coefficient:±100ppm/℃ Operating Temperature Range:-55℃~+155℃ Operating Temperature Range:-55℃~+155℃; Manufacturer: UNI-ROYAL(厚声); Symbol: ERJ2RKF4700X; AddInBom: yes; ModelId: efdecb7dae4442949d28eecaf748420f; ModelName: R0402_L1.0-W0.5-H0.4; ModelTransform: 39.37,19.685,0,0,0,0,0,0,0; Tolerance: ±1%
R158 R233 = 0402WGF0000TCE: Type:Thick Film Resistor Resistance:0Ω Tolerance:±1% Tolerance:±1% Power(Watts):62.5mW Voltage-Supply(Max):50V Temperature Coefficient:±800ppm/℃ Temperature Coefficient:±800ppm/℃ Operating Temperature:-55℃~+155℃ Operating Temperature:-55℃~+155℃; Manufacturer: UNI-ROYAL(厚声); AddInBom: yes; ModelId: efdecb7dae4442949d28eecaf748420f; ModelName: R0402_L1.0-W0.5-H0.4; ModelTransform: 39.37,19.685,0,0,0,0,0,0,0; Tolerance: ±1%; Power(Watts): 62.5mW; Voltage-Supply(Max): 50V
R235 R236 R249-R251 = 0402WGF1002TCE: Type:Thick Film Resistors Resistance:10kΩ Tolerance:±1% Tolerance:±1% Power(Watts): Overload Voltage (Max): Temperature Coefficient:±100ppm/℃ Temperature Coefficient:±100ppm/℃ Operating Temperature Range:-55℃~+155℃ Operating Temperature Range:-55℃~+155℃; Manufacturer: UNI-ROYAL(厚声); Add into BOM: no; ConvertToPcb: yes; ModelId: efdecb7dae4442949d28eecaf748420f; ModelName: R0402_L1.0-W0.5-H0.4; ModelTransform: 39.37,19.685,0,0,0,0,0,0,0; Tolerance: ±1%
R238 R240 R241 R243-R245 = 0402WGF1002TCE: Type:Thick Film Resistors Resistance:10kΩ Tolerance:±1% Tolerance:±1% Power(Watts): Overload Voltage (Max): Temperature Coefficient:±100ppm/℃ Temperature Coefficient:±100ppm/℃ Operating Temperature Range:-55℃~+155℃ Operating Temperature Range:-55℃~+155℃; Manufacturer: UNI-ROYAL(厚声); Add into BOM: yes; ModelId: efdecb7dae4442949d28eecaf748420f; ModelName: R0402_L1.0-W0.5-H0.4; ModelTransform: 39.37,19.685,0,0,0,0,0,0,0; Tolerance: ±1%
R252 R253 = 0402WGF1002TCE: Type:Thick Film Resistors Resistance:10kΩ Tolerance:±1% Tolerance:±1% Power(Watts): Overload Voltage (Max): Temperature Coefficient:±100ppm/℃ Temperature Coefficient:±100ppm/℃ Operating Temperature Range:-55℃~+155℃ Operating Temperature Range:-55℃~+155℃; Manufacturer: UNI-ROYAL(厚声); AddInBom: yes; ModelId: efdecb7dae4442949d28eecaf748420f; ModelName: R0402_L1.0-W0.5-H0.4; ModelTransform: 39.37,19.685,0,0,0,0,0,0,0; Tolerance: ±1%
R257 = 0402WGF220JTCE: Type:Thick Film Resistors Resistance:22Ω Tolerance:±1% Tolerance:±1% Power(Watts): Overload Voltage (Max): Temperature Coefficient:±100ppm/℃ Temperature Coefficient:±100ppm/℃ Operating Temperature Range:-55℃~+155℃ Operating Temperature Range:-55℃~+155℃; Manufacturer: UNI-ROYAL(厚声); Add into BOM: no; ConvertToPcb: yes; ModelId: efdecb7dae4442949d28eecaf748420f; ModelName: R0402_L1.0-W0.5-H0.4; ModelTransform: 39.37,19.685,0,0,0,0,0,0,0; Tolerance: ±1%
U1 U112 = PZ2.54-2*4: Pin Structure:2x4P Pitch:2.54mm Number of Rows:双排 Number of Pins:8P; Manufacturer: ZHOURI(洲日); Check: true; 3D Model: 47b5ce995b664298ab05f1b74b77106f; 3D Model Transform: 399.999,200,0,0,0,0,0,0,-118.11; Pin Structure: 2x4P; Pitch: 2.54mm; AddInBom: yes; ModelName: HDR-TH_8P-P2.54-M-LI-2X4P
U99 = W25Q128JVSIQ: Interface:SPI Memory Size:128Mbit Clock Frequency:133MHz Voltage - Supply:2.7V~3.6V Voltage - Supply:2.7V~3.6V Standby Supply Current:1uA Program / Erase Cycles:100,000 Cycles Page Programming Time (Tpp):3ms Block Erase Time(tBE):120ms@(32KB) Data Retenti; Manufacturer: Winbond(华邦); Symbol: W25Q128JVSIQTR; AddInBom: yes; ModelId: 7b3104f4a302484e875593c5ba7bd3db; ModelName: SOIC-8_L5.3-W5.3-H1.9-LS7.9-P1.27; ModelTransform: 208.661,311.25654,0,0,0,0,-0.0005,0.0005,0; Interface: SPI; Clock Frequency: 133MHz; Standby Supply Current: 1uA; Page Programming Time (Tpp): 3ms; Data Retention - TDR (Year): 20 Years
U100 = T120F324C3: Relevance: []; AddInBom: yes
X7 = OT322550MJBA4SL: Frequency:50MHz Normal temperature Frequency Tolerance:±10ppm Normal temperature Frequency Tolerance:±10ppm Output Type:CMOS Voltage - Supply:1.8V~3.3V Voltage - Supply:1.8V~3.3V Frequency Stability:±20ppm Frequency Stability:±20ppm Operating Temperature:; Manufacturer: YXC(扬兴晶振); AddInBom: yes; ModelId: 3d8e5f33629249f9a4089449c02742d4; ModelName: OSC-SMD_4P-L3.2-W2.5-H1.0; ModelTransform: 125.984,98.425,0,0,0,0,0,0,0; Normal temperature Frequency Tolerance: ±10ppm; Output Type: CMOS; Frequency Stability: ±20ppm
